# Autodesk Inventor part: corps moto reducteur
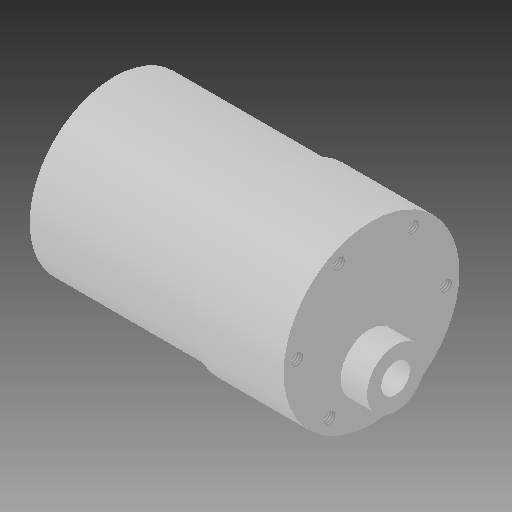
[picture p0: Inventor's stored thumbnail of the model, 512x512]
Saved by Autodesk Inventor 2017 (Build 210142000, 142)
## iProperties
Part Number: corps moto reducteur
Material: Générique
Document SubType Name: Modeling
Designer: ficho
Density: 1 g/cm^3
Appearance: Par défaut
Mass: 53.4331 g
Surface Area: 85.5661 cm^2
Volume: 53.4331 cm^3
Author: ficho
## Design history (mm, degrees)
sketch "Esquisse1"
  geometry: L1 (0, 0)-(0, 18.25); L2 (0, 18.25)-(-19, 18.25); L3 (-19, 18.25)-(-19, 17.5); L4 (-19, 17.5)-(-53.5, 17.5); L5 (-53.5, 17.5)-(-53.5, 0); L6 (-53.5, 0)-(0, 0)
  constraints: 12 end point, 5 perpendicular, 1 vertical
  dimensions: "d0" = 18.25 distance between parallel lines of L2 L6; "d1" = 19 distance between parallel lines of L3 L1; "d2" = 17.5 distance between parallel lines of L6 L4; "d3" = 53.5 distance between parallel lines of L1 L5
revolve "Révolution1" sketch "Esquisse1" stored, may be unused: angle "d4" = 90 deg
sketch "Esquisse2" dims "d8" = 31
  geometry: C1 r 6.6 at (0, -7); C2 r 18.25 at (0, 0) reference; 9 further points
  constraints: 1 centre point, 1 coincident, 10 other
  dimensions: "d7" = 7 distance of point (0, 0) C1.centre; "d9" = 360 deg dimension on point (0, 0) point (-15.459, 1.123) (derived)
hole "Perçage1" sketch "Esquisse2" at (-15.459, 1.123), (-6.757, 13.95), (8.702, 12.827), (15.459, -1.123), (6.757, -13.95), (-8.702, -12.827) diameter "d10" = 2.459; stored, may be unused: countersink angle "d14" = 90 deg, drill point angle "d16" = 118 deg; dims "d11" = 3, "d12" = 4, "d13" = 2, "d15" = 4
sketch "Esquisse3"
  geometry: C1 r 6 at (-0.448, -6.986); 1 further point
  constraints: 1 centre point
  dimensions: "d24" = 12 diameter of C1; "d25" = 7 distance of C1.centre point (0, 0)
extrude "Extrusion1" join sketch "Esquisse3" distance "d19" = 5.5; taper "d20" = 0 deg
sketch "Esquisse4"
  geometry: C1 r 6 at (0, 0) reference; C2 r 6.6 at (-0.507, 0.018) reference; C3 r 3 at (-0.507, 0.018)
  constraints: 1 centre point, 1 coincident
  dimensions: "d26" = 6 diameter of C3
extrude "Extrusion2" cut sketch "Esquisse4" distance "d22" = 5; taper "d23" = 0 deg
node "Solide1"
node "Boucle projetée1"
node "Référence1"
